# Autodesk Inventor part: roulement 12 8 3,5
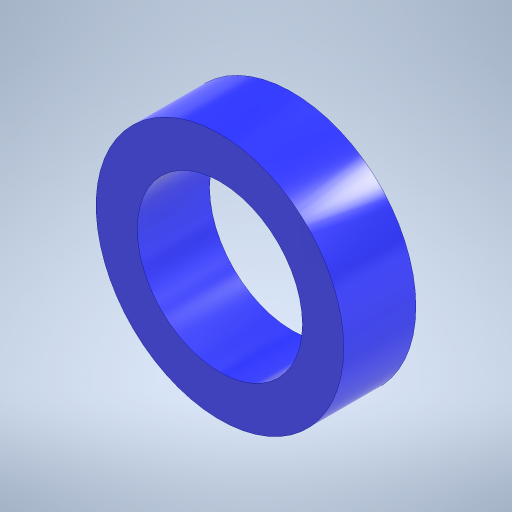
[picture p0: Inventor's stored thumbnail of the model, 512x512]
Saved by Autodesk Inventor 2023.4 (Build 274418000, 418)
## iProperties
Created: 2025-06
Part Number: roulement 12 8 3,5
Material: Générique
Document SubType Name: Modeling
Designer: mel
Density: 1 g/cm^3
Appearance: Bleu - Peinture murale - Brillant
Author: mel
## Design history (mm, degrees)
sketch "Esquisse1"
  geometry: C1 r 6 at (0.214, 0); C2 r 4 at (0.214, 0); 1 further point
  constraints: 2 centre point, 1 coincident
  dimensions: "d0" = 12 diameter of C1; "d1" = 8 diameter of C2
extrude "Extrusion1" new body sketch "Esquisse1" distance "d2" = 3.5; taper "d3" = 0 deg
node "Solide1"
